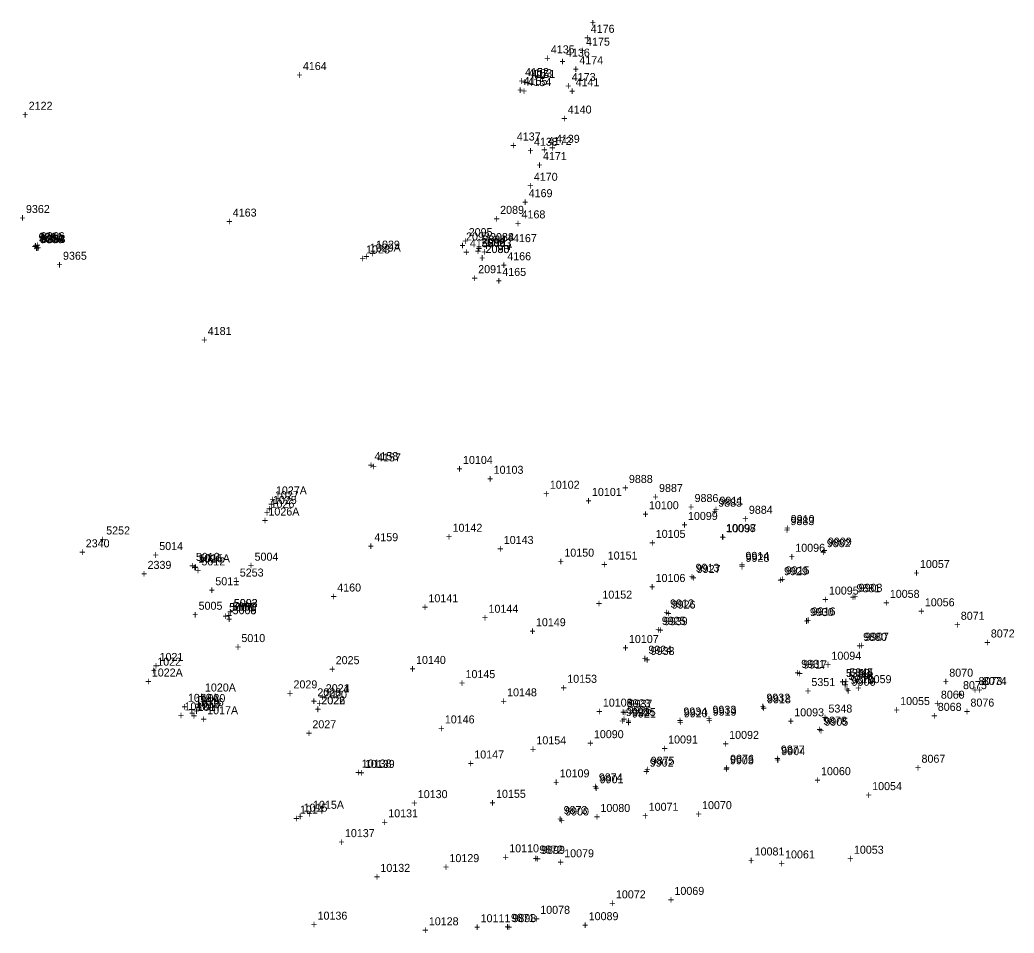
# Model space of a CAD drawing. Extents: x 1136220 to 1137808, y 528804 to 531215.
# Drawn here: x 1137109.6 to 1137420.1, y 529073.9 to 529359 of the extents above; entities that cross this region are included whole.
import ezdxf

# ---------------------------------------------------------------- set-up
doc = ezdxf.new("R2010")
doc.units = 0
for name, color, linetype in [('S_Annotation_Label', 7, 'Continuous'), ('S_Buildings_SillElevation', 7, 'Continuous'), ('S_Curb_Type_3', 7, 'Continuous'), ('S_Drainage_CB', 7, 'Continuous'), ('S_Drainage_Culvert_Top', 7, 'Continuous'), ('S_Drainage_Invert', 7, 'Continuous'), ('S_Drainage_MH', 7, 'Continuous'), ('S_Drainage_Sump', 7, 'Continuous'), ('S_Ground_Elevation', 7, 'Continuous'), ('S_Ground_LevelString', 7, 'Continuous'), ('S_Ground_SpotElevation', 7, 'Continuous'), ('S_Property_RockBoulder', 7, 'Continuous'), ('S_Roadway_Edge_Pavement', 7, 'Continuous'), ('S_Utilities_Gas_Gate', 7, 'Continuous'), ('S_Utilities_UG_Gas_Line', 7, 'Continuous'), ('S_Utilities_UG_Sanitary_MH', 7, 'Continuous'), ('S_Utilities_UG_Water_Gate', 7, 'Continuous'), ('S_Utilities_UG_Water_Line', 7, 'Continuous')]:
    doc.layers.add(name, color=color, linetype=linetype)

msp = doc.modelspace()

# ---------------------------------------------------------------- texts
at = {"layer": 'S_Annotation_Label'}
for s, p in [('10081', (1137339.05, 529098.18)), ('+', (1137336.99, 529095.43)), ('10089', (1137287.22, 529077.98)), ('+', (1137285.15, 529075.23))]:
    msp.add_text(s, height=2.5, dxfattribs=at).set_placement(p)
at = {"layer": 'S_Buildings_SillElevation'}
for s, p in [('4164', (1137197.97, 529343.34)), ('+', (1137195.91, 529340.59)), ('4163', (1137176.07, 529297.6)), ('+', (1137174.01, 529294.85)), ('4181', (1137168.25, 529260.63)), ('+', (1137166.19, 529257.88))]:
    msp.add_text(s, height=2.5, dxfattribs=at).set_placement(p)
at = {"layer": 'S_Curb_Type_3'}
for s, p in [('9911', (1137328.06, 529207.67)), ('+', (1137326, 529204.92)), ('9910', (1137350.32, 529201.93)), ('+', (1137348.26, 529199.18)), ('9909', (1137361.93, 529194.9)), ('+', (1137359.87, 529192.15)), ('9928', (1137336.22, 529189.85)), ('9927', (1137320.96, 529186.36)), ('+', (1137334.15, 529187.1)), ('9929', (1137348.23, 529185.67)), ('+', (1137318.9, 529183.61)), ('+', (1137346.17, 529182.92)), ('9908', (1137371.51, 529180.5)), ('+', (1137369.45, 529177.75)), ('9926', (1137313.15, 529175.24)), ('9930', (1137356.32, 529172.91)), ('9939', (1137310.69, 529170.05)), ('+', (1137311.09, 529172.49)), ('+', (1137354.26, 529170.16)), ('+', (1137308.63, 529167.3)), ('9907', (1137373.48, 529165.22)), ('9938', (1137306.57, 529160.78)), ('+', (1137371.42, 529162.47)), ('+', (1137304.51, 529158.03)), ('9931', (1137353.59, 529156.74)), ('+', (1137351.53, 529153.99)), ('9906', (1137369.35, 529151.15)), ('+', (1137367.29, 529148.4)), ('9932', (1137342.7, 529146.17)), ('9936', (1137299.35, 529142.28)), ('9937', (1137299.67, 529144.31)), ('9935', (1137300.72, 529141.71)), ('9934', (1137316.79, 529141.86)), ('9933', (1137325.88, 529142.41)), ('+', (1137340.63, 529143.42)), ('+', (1137297.29, 529139.53)), ('+', (1137297.61, 529141.56)), ('+', (1137298.66, 529138.96)), ('+', (1137314.73, 529139.11)), ('+', (1137323.82, 529139.66)), ('9905', (1137360.83, 529138.67)), ('+', (1137358.77, 529135.92)), ('9904', (1137347.38, 529129.5)), ('9902', (1137306.3, 529125.91)), ('9903', (1137331.33, 529126.65)), ('+', (1137345.31, 529126.75)), ('+', (1137329.26, 529123.9)), ('9901', (1137290.65, 529120.72)), ('+', (1137304.24, 529123.16)), ('+', (1137288.59, 529117.97)), ('9900', (1137279.87, 529110.67)), ('+', (1137277.81, 529107.92)), ('9899', (1137272.37, 529098.67)), ('+', (1137270.3, 529095.92)), ('9898', (1137263.41, 529077.36)), ('+', (1137261.35, 529074.61))]:
    msp.add_text(s, height=2.5, dxfattribs=at).set_placement(p)
at = {"layer": 'S_Drainage_CB'}
for s, p in [('9366', (1137116.11, 529290.23)), ('+', (1137114.05, 529287.48)), ('5015A', (1137165.51, 529189.71)), ('+', (1137163.45, 529186.96)), ('5344', (1137368.63, 529154.06)), ('+', (1137366.57, 529151.31))]:
    msp.add_text(s, height=2.5, dxfattribs=at).set_placement(p)
at = {"layer": 'S_Drainage_Culvert_Top'}
for s, p in [('2122', (1137112.33, 529330.95)), ('+', (1137110.27, 529328.2)), ('9362', (1137111.48, 529298.72)), ('2089', (1137259.57, 529298.45)), ('+', (1137109.42, 529295.97)), ('+', (1137257.51, 529295.7)), ('2095', (1137249.75, 529291.5)), ('9361', (1137115.53, 529290.06)), ('9364', (1137116.2, 529289.33)), ('1029', (1137220.82, 529287.59)), ('+', (1137247.69, 529288.75)), ('2093', (1137248.92, 529290.14)), ('2092', (1137253.71, 529288.36)), ('2094', (1137254.03, 529289.17)), ('2088', (1137256.41, 529289.96)), ('+', (1137113.47, 529287.31)), ('+', (1137114.14, 529286.58)), ('+', (1137218.76, 529284.84)), ('+', (1137246.85, 529287.39)), ('+', (1137251.65, 529285.61)), ('+', (1137251.97, 529286.42)), ('+', (1137254.34, 529287.21)), ('2090', (1137255.04, 529286.24)), ('9365', (1137123.05, 529284.13)), ('+', (1137252.98, 529283.49)), ('+', (1137120.99, 529281.38)), ('2091', (1137252.71, 529279.94)), ('+', (1137250.64, 529277.19)), ('1027A', (1137189.54, 529210.87)), ('+', (1137187.48, 529208.12)), ('1026A', (1137187.2, 529204.28)), ('+', (1137185.14, 529201.53)), ('5014', (1137153.1, 529193.51)), ('+', (1137151.04, 529190.76)), ('5013', (1137164.55, 529190.14)), ('5012', (1137166.28, 529188.72)), ('5004', (1137182.87, 529190.19)), ('+', (1137162.49, 529187.39)), ('+', (1137164.21, 529185.97)), ('+', (1137180.81, 529187.44)), ('5011', (1137170.62, 529182.52)), ('+', (1137168.56, 529179.77)), ('5003', (1137176.36, 529175.75)), ('5005', (1137165.4, 529174.88)), ('+', (1137174.3, 529173)), ('5006', (1137174.95, 529174.45)), ('5009', (1137176.03, 529173.48)), ('+', (1137163.34, 529172.13)), ('+', (1137172.89, 529171.7)), ('+', (1137173.97, 529170.73)), ('5010', (1137178.76, 529164.79)), ('+', (1137176.7, 529162.04)), ('2025', (1137208.21, 529157.89)), ('1022A', (1137150.78, 529154.04)), ('+', (1137206.15, 529155.14)), ('5350', (1137367.57, 529153.9)), ('+', (1137148.72, 529151.29)), ('5351', (1137356.77, 529151.06)), ('5347', (1137368.36, 529152.99)), ('1020A', (1137167.37, 529149.36)), ('2029', (1137195.03, 529150.33)), ('2028', (1137202.48, 529147.87)), ('2024', (1137205.12, 529149.13)), ('+', (1137354.71, 529148.31)), ('+', (1137365.51, 529151.15)), ('+', (1137366.3, 529150.24)), ('1019A', (1137162.06, 529146.14)), ('+', (1137165.31, 529146.61)), ('+', (1137192.97, 529147.58)), ('+', (1137200.42, 529145.12)), ('+', (1137203.06, 529146.38)), ('2026', (1137203.75, 529145.34)), ('+', (1137160, 529143.39)), ('1018A', (1137160.99, 529143.45)), ('1017A', (1137168.06, 529142.25)), ('+', (1137201.68, 529142.59)), ('5348', (1137362.1, 529142.79)), ('+', (1137158.93, 529140.7)), ('+', (1137166, 529139.5)), ('+', (1137360.04, 529140.04)), ('2027', (1137200.93, 529137.88)), ('+', (1137198.87, 529135.13)), ('1015A', (1137201.13, 529112.75)), ('+', (1137199.07, 529110))]:
    msp.add_text(s, height=2.5, dxfattribs=at).set_placement(p)
at = {"layer": 'S_Drainage_Invert'}
for s, p in [('9360', (1137115.39, 529289.79)), ('9363', (1137116.39, 529289.43)), ('2086', (1137253.71, 529288.36)), ('2087', (1137253.98, 529289.18)), ('2084', (1137256.39, 529289.96)), ('+', (1137113.33, 529287.04)), ('+', (1137114.33, 529286.68)), ('1029A', (1137218.86, 529286.67)), ('+', (1137251.65, 529285.61)), ('+', (1137251.92, 529286.43)), ('+', (1137254.33, 529287.21)), ('2085', (1137255.02, 529286.21)), ('+', (1137216.8, 529283.92)), ('+', (1137252.96, 529283.46)), ('1026', (1137187.87, 529206.71)), ('1027', (1137189.21, 529209.39)), ('+', (1137187.15, 529206.64)), ('+', (1137185.81, 529203.96)), ('5002', (1137176.41, 529175.72)), ('+', (1137174.34, 529172.97)), ('5007', (1137174.91, 529174.44)), ('5008', (1137176.02, 529173.48)), ('+', (1137172.85, 529171.69)), ('+', (1137173.96, 529170.73)), ('1022', (1137152.48, 529157.41)), ('+', (1137150.42, 529154.66)), ('5349', (1137367.62, 529153.88)), ('5346', (1137368.43, 529153)), ('2023', (1137202.49, 529147.85)), ('2021', (1137205.1, 529149.13)), ('+', (1137365.56, 529151.13)), ('+', (1137366.37, 529150.25)), ('1019', (1137164.32, 529145.3)), ('1020', (1137166.31, 529146.06)), ('+', (1137200.43, 529145.1)), ('+', (1137203.04, 529146.38)), ('2022', (1137203.72, 529145.37)), ('+', (1137162.26, 529142.55)), ('+', (1137164.25, 529143.31)), ('1018', (1137164.45, 529144.16)), ('1017', (1137165.07, 529143.32)), ('+', (1137201.65, 529142.62)), ('+', (1137162.39, 529141.41)), ('+', (1137163.01, 529140.57)), ('1015', (1137198.19, 529111.85)), ('+', (1137196.13, 529109.1))]:
    msp.add_text(s, height=2.5, dxfattribs=at).set_placement(p)
at = {"layer": 'S_Drainage_MH'}
for s, p in [('5000', (1137175.99, 529174.64)), ('+', (1137173.93, 529171.89))]:
    msp.add_text(s, height=2.5, dxfattribs=at).set_placement(p)
at = {"layer": 'S_Drainage_Sump'}
for s, p in [('9359', (1137115.84, 529289.31)), ('+', (1137113.78, 529286.56)), ('1028', (1137217.7, 529286.1)), ('+', (1137215.64, 529283.35)), ('1025', (1137188.6, 529207.9)), ('+', (1137186.54, 529205.15)), ('1024', (1137165.3, 529189.6)), ('+', (1137163.24, 529186.85)), ('5001', (1137175.91, 529174.61)), ('+', (1137173.85, 529171.86)), ('1021', (1137153.2, 529158.9)), ('+', (1137151.14, 529156.15)), ('5345', (1137368.61, 529154.07)), ('+', (1137366.55, 529151.32)), ('1016', (1137165.81, 529144.81)), ('+', (1137163.75, 529142.06)), ('1014', (1137197.02, 529111.25)), ('+', (1137194.96, 529108.5))]:
    msp.add_text(s, height=2.5, dxfattribs=at).set_placement(p)
at = {"layer": 'S_Ground_Elevation'}
for s, p in [('10142', (1137244.7, 529199.22)), ('+', (1137242.63, 529196.47)), ('10143', (1137260.7, 529195.42)), ('+', (1137258.64, 529192.67)), ('10150', (1137279.62, 529191.45)), ('+', (1137277.56, 529188.7)), ('10151', (1137293.16, 529190.56)), ('+', (1137291.1, 529187.81)), ('10057', (1137390.68, 529187.91)), ('+', (1137388.62, 529185.16)), ('10141', (1137237.17, 529177.21)), ('10152', (1137291.5, 529178.35)), ('10058', (1137381.26, 529178.59)), ('10056', (1137392.2, 529175.96)), ('+', (1137235.11, 529174.46)), ('10144', (1137255.93, 529173.94)), ('+', (1137289.44, 529175.6)), ('+', (1137379.2, 529175.84)), ('+', (1137390.14, 529173.21)), ('+', (1137253.87, 529171.19)), ('10149', (1137270.75, 529169.74)), ('8071', (1137403.43, 529171.75)), ('+', (1137268.69, 529166.99)), ('+', (1137401.37, 529169)), ('8072', (1137412.81, 529166.22)), ('+', (1137410.75, 529163.47)), ('10140', (1137233.3, 529157.96)), ('+', (1137231.23, 529155.21)), ('8070', (1137399.84, 529153.98)), ('10145', (1137248.75, 529153.54)), ('10153', (1137280.52, 529152.07)), ('10059', (1137372.49, 529151.97)), ('+', (1137397.78, 529151.23)), ('8073', (1137408.96, 529151.38)), ('+', (1137246.69, 529150.79)), ('10148', (1137261.74, 529147.85)), ('+', (1137278.46, 529149.32)), ('+', (1137370.43, 529149.22)), ('+', (1137406.9, 529148.63)), ('+', (1137259.68, 529145.1)), ('10055', (1137384.49, 529145.13)), ('8069', (1137397.21, 529147.12)), ('8076', (1137406.45, 529144.65)), ('+', (1137382.43, 529142.38)), ('+', (1137395.15, 529144.37)), ('8068', (1137396.24, 529143.32)), ('+', (1137404.39, 529141.9)), ('10146', (1137242.29, 529139.4)), ('+', (1137394.18, 529140.57)), ('+', (1137240.22, 529136.65)), ('10154', (1137270.89, 529132.87)), ('+', (1137268.83, 529130.12)), ('10147', (1137251.49, 529128.45)), ('8067', (1137391.16, 529127.12)), ('+', (1137249.42, 529125.7)), ('10060', (1137359.78, 529123.24)), ('+', (1137389.1, 529124.37)), ('+', (1137357.72, 529120.49)), ('10054', (1137375.75, 529118.57)), ('10155', (1137258.28, 529116.17)), ('+', (1137373.69, 529115.82)), ('+', (1137256.22, 529113.42)), ('10080', (1137290.89, 529111.76)), ('10071', (1137305.96, 529112.12)), ('10070', (1137322.62, 529112.64)), ('+', (1137288.83, 529109.01)), ('+', (1137303.9, 529109.37)), ('+', (1137320.56, 529109.89)), ('10053', (1137370.05, 529098.72)), ('10079', (1137279.57, 529097.61)), ('10061', (1137348.55, 529097.26)), ('+', (1137367.98, 529095.97)), ('+', (1137277.51, 529094.86)), ('+', (1137346.49, 529094.51)), ('10069', (1137314, 529085.87)), ('10072', (1137295.72, 529084.79)), ('+', (1137311.93, 529083.12)), ('10078', (1137272.09, 529079.96)), ('+', (1137293.66, 529082.04)), ('+', (1137270.03, 529077.21))]:
    msp.add_text(s, height=2.5, dxfattribs=at).set_placement(p)
at = {"layer": 'S_Ground_LevelString'}
for s, p in [('10104', (1137247.97, 529220.39)), ('+', (1137245.91, 529217.64)), ('10103', (1137257.54, 529217.31)), ('+', (1137255.48, 529214.56)), ('10102', (1137275.08, 529212.65)), ('10101', (1137288.24, 529210.41)), ('+', (1137273.02, 529209.9)), ('+', (1137286.18, 529207.66)), ('10100', (1137306.04, 529206.26)), ('+', (1137303.98, 529203.51)), ('10099', (1137318.22, 529202.91)), ('+', (1137316.16, 529200.16)), ('10098', (1137330.1, 529199.14)), ('10097', (1137330.24, 529199.04)), ('10105', (1137308.16, 529197.31)), ('+', (1137328.04, 529196.39)), ('+', (1137328.18, 529196.29)), ('+', (1137306.1, 529194.56)), ('10096', (1137351.74, 529192.97)), ('+', (1137349.68, 529190.22)), ('10106', (1137308.12, 529183.55)), ('+', (1137306.06, 529180.8)), ('10095', (1137362.24, 529179.62)), ('+', (1137360.18, 529176.87)), ('10107', (1137299.79, 529164.5)), ('+', (1137297.73, 529161.76)), ('10094', (1137363.03, 529159.28)), ('+', (1137360.97, 529156.53)), ('10108', (1137291.64, 529144.64)), ('+', (1137289.58, 529141.89)), ('10093', (1137351.42, 529141.62)), ('+', (1137349.36, 529138.87)), ('10090', (1137288.84, 529134.79)), ('10091', (1137312.03, 529133.13)), ('10092', (1137331.09, 529134.56)), ('+', (1137286.78, 529132.04)), ('+', (1137309.97, 529130.38)), ('+', (1137329.03, 529131.81)), ('10138', (1137216.36, 529125.63)), ('10139', (1137217.32, 529125.51)), ('+', (1137214.3, 529122.88)), ('+', (1137215.25, 529122.76)), ('10109', (1137278.17, 529122.56)), ('+', (1137276.1, 529119.81)), ('10130', (1137233.85, 529116.08)), ('+', (1137231.79, 529113.33)), ('10131', (1137224.62, 529110.09)), ('+', (1137222.55, 529107.34)), ('10137', (1137211.09, 529103.9)), ('+', (1137209.03, 529101.15)), ('10110', (1137262.4, 529099.16)), ('10129', (1137243.74, 529096.1)), ('+', (1137260.34, 529096.41)), ('10132', (1137222.17, 529093.05)), ('+', (1137241.67, 529093.35)), ('+', (1137220.11, 529090.3)), ('10136', (1137202.55, 529078.13)), ('10128', (1137237.29, 529076.38)), ('10111', (1137253.47, 529077.33)), ('+', (1137200.49, 529075.38)), ('+', (1137235.23, 529073.63)), ('+', (1137251.41, 529074.58))]:
    msp.add_text(s, height=2.5, dxfattribs=at).set_placement(p)
at = {"layer": 'S_Ground_SpotElevation'}
for s, p in [('4135', (1137275.4, 529348.55)), ('4136', (1137280.13, 529347.53)), ('+', (1137273.34, 529345.8)), ('+', (1137278.07, 529344.78)), ('4137', (1137264.77, 529321.35)), ('4138', (1137270.12, 529319.7)), ('+', (1137262.7, 529318.6)), ('+', (1137268.06, 529316.95)), ('8074', (1137410.32, 529151.38)), ('8075', (1137404.12, 529150.09)), ('+', (1137408.26, 529148.63)), ('+', (1137402.06, 529147.34))]:
    msp.add_text(s, height=2.5, dxfattribs=at).set_placement(p)
at = {"layer": 'S_Property_RockBoulder'}
for s, p in [('+', (1137287.54, 529356.9)), ('4176', (1137287.86, 529354.96)), ('+', (1137285.8, 529352.21)), ('4175', (1137286.41, 529350.96)), ('+', (1137284.35, 529348.21)), ('4174', (1137284.3, 529345.15)), ('+', (1137282.24, 529342.4)), ('4173', (1137281.94, 529339.93)), ('+', (1137279.88, 529337.18)), ('4172', (1137274.46, 529319.98)), ('+', (1137272.4, 529317.23)), ('4171', (1137272.93, 529315.24)), ('+', (1137270.87, 529312.49)), ('4170', (1137270.09, 529308.78)), ('+', (1137268.03, 529306.03)), ('4169', (1137268.48, 529303.66)), ('+', (1137266.42, 529300.91)), ('4168', (1137266.25, 529297.03)), ('+', (1137264.19, 529294.28)), ('4167', (1137263.58, 529289.62)), ('+', (1137261.52, 529286.87)), ('4166', (1137261.79, 529283.97)), ('+', (1137259.73, 529281.22)), ('4165', (1137260.24, 529279.08)), ('+', (1137258.18, 529276.33))]:
    msp.add_text(s, height=2.5, dxfattribs=at).set_placement(p)
at = {"layer": 'S_Roadway_Edge_Pavement'}
for s, p in [('4141', (1137283.13, 529338.29)), ('+', (1137281.07, 529335.54)), ('4140', (1137280.69, 529329.76)), ('+', (1137278.62, 529327.01)), ('4139', (1137276.98, 529320.63)), ('+', (1137274.92, 529317.88)), ('9888', (1137299.78, 529214.46)), ('+', (1137297.72, 529211.71)), ('9887', (1137309.19, 529211.64)), ('+', (1137307.13, 529208.89)), ('9886', (1137320.29, 529208.5)), ('9885', (1137327.68, 529207.05)), ('+', (1137318.23, 529205.75)), ('+', (1137325.62, 529204.3)), ('9884', (1137337.25, 529204.83)), ('+', (1137335.18, 529202.08)), ('9883', (1137350.23, 529201.3)), ('5252', (1137136.53, 529198.38)), ('+', (1137348.17, 529198.55)), ('+', (1137134.47, 529195.63)), ('9882', (1137361.59, 529194.42)), ('+', (1137359.53, 529191.67)), ('9914', (1137336.19, 529190.44)), ('5253', (1137178.26, 529185.24)), ('9913', (1137320.6, 529186.73)), ('+', (1137334.13, 529187.69)), ('9915', (1137348.75, 529185.94)), ('+', (1137176.2, 529182.49)), ('+', (1137318.54, 529183.98)), ('+', (1137346.69, 529183.19)), ('9881', (1137370.84, 529180.34)), ('9912', (1137312.64, 529175.6)), ('+', (1137368.78, 529177.59)), ('9916', (1137356.86, 529173.12)), ('9925', (1137310.05, 529170.19)), ('+', (1137310.58, 529172.85)), ('+', (1137354.79, 529170.37)), ('+', (1137307.99, 529167.44)), ('9880', (1137372.94, 529165.17)), ('9924', (1137305.85, 529161.15)), ('+', (1137370.88, 529162.42)), ('+', (1137303.79, 529158.4)), ('9917', (1137354.21, 529156.54)), ('+', (1137352.15, 529153.79)), ('9879', (1137368.98, 529151.68)), ('+', (1137366.92, 529148.93)), ('9918', (1137342.93, 529145.68)), ('9922', (1137298.84, 529141.7)), ('9923', (1137299.07, 529144.44)), ('9919', (1137325.96, 529141.81)), ('+', (1137340.87, 529142.93)), ('+', (1137296.78, 529138.95)), ('+', (1137297.01, 529141.69)), ('9921', (1137300.74, 529141.24)), ('9920', (1137316.93, 529141.3)), ('+', (1137323.9, 529139.06)), ('9878', (1137360.43, 529139.02)), ('+', (1137298.68, 529138.49)), ('+', (1137314.87, 529138.55)), ('+', (1137358.37, 529136.27)), ('9877', (1137347.23, 529130)), ('9875', (1137306.59, 529126.51)), ('9876', (1137331.39, 529127.1)), ('+', (1137345.17, 529127.25)), ('+', (1137304.53, 529123.76)), ('+', (1137329.33, 529124.35)), ('9874', (1137290.39, 529121.29)), ('+', (1137288.33, 529118.54)), ('9873', (1137279.39, 529111.1)), ('+', (1137277.33, 529108.35)), ('9872', (1137271.8, 529098.78)), ('+', (1137269.74, 529096.03)), ('9871', (1137262.94, 529077.46)), ('+', (1137260.88, 529074.71))]:
    msp.add_text(s, height=2.5, dxfattribs=at).set_placement(p)
at = {"layer": 'S_Utilities_Gas_Gate'}
for s, p in [('2339', (1137149.46, 529187.63)), ('+', (1137147.4, 529184.88))]:
    msp.add_text(s, height=2.5, dxfattribs=at).set_placement(p)
at = {"layer": 'S_Utilities_UG_Gas_Line'}
for s, p in [('2340', (1137130.15, 529194.37)), ('+', (1137128.09, 529191.62))]:
    msp.add_text(s, height=2.5, dxfattribs=at).set_placement(p)
at = {"layer": 'S_Utilities_UG_Sanitary_MH'}
for s, p in [('2083', (1137255.68, 529288.09)), ('+', (1137253.62, 529285.35)), ('2020', (1137204.29, 529147.21)), ('+', (1137202.23, 529144.47))]:
    msp.add_text(s, height=2.5, dxfattribs=at).set_placement(p)
at = {"layer": 'S_Utilities_UG_Water_Gate'}
for s, p in [('4153', (1137268.37, 529341.11)), ('+', (1137266.31, 529338.36)), ('4159', (1137220.28, 529196.28)), ('+', (1137218.22, 529193.53)), ('4160', (1137208.69, 529180.56)), ('+', (1137206.63, 529177.81))]:
    msp.add_text(s, height=2.5, dxfattribs=at).set_placement(p)
at = {"layer": 'S_Utilities_UG_Water_Line'}
for s, p in [('4152', (1137267.35, 529341.47)), ('4151', (1137269.31, 529340.86)), ('+', (1137265.29, 529338.72)), ('4155', (1137266.89, 529338.65)), ('+', (1137267.25, 529338.11)), ('4154', (1137268.1, 529338.33)), ('+', (1137264.83, 529335.9)), ('+', (1137266.04, 529335.58)), ('4156', (1137250.11, 529288.04)), ('+', (1137248.05, 529285.29)), ('4158', (1137220.32, 529221.57)), ('4157', (1137221.14, 529221.18)), ('+', (1137218.26, 529218.82)), ('+', (1137219.08, 529218.43))]:
    msp.add_text(s, height=2.5, dxfattribs=at).set_placement(p)

doc.saveas('drawing.dxf')
